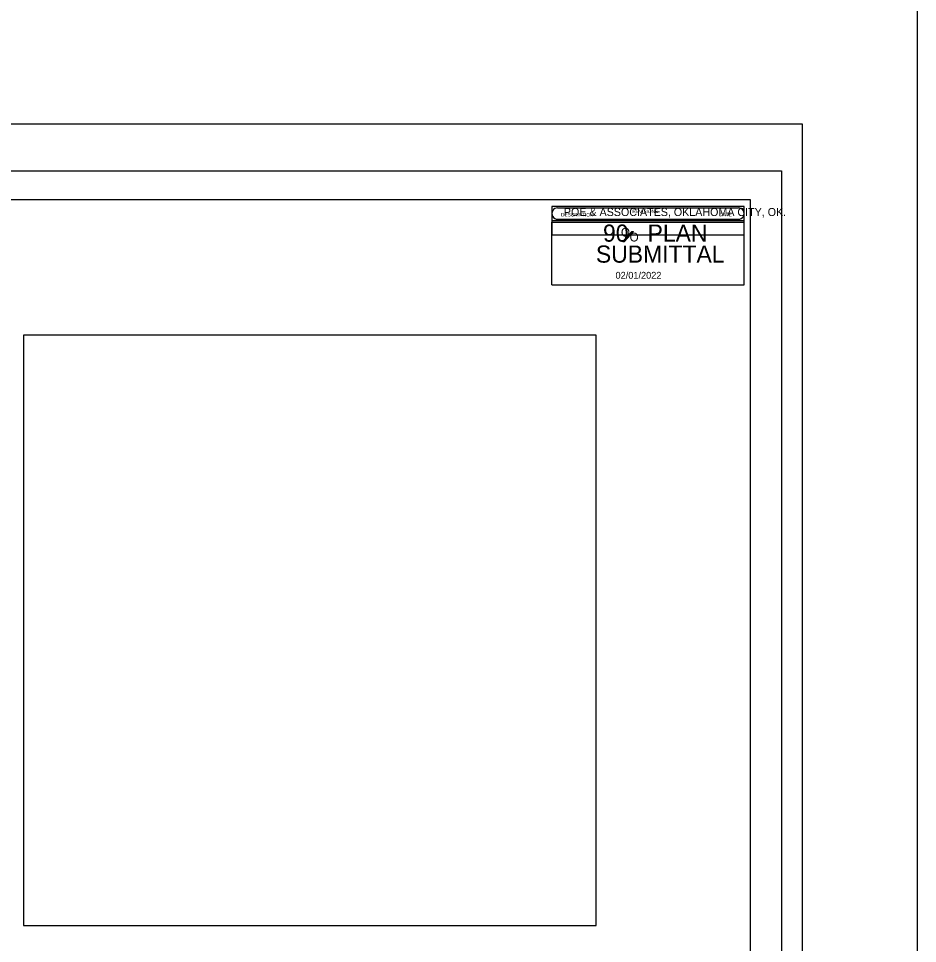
# Model space of a CAD drawing. Extents: x 12310.9 to 12354.4, y 579 to 640.5.
# Drawn here: x 12338.64 to 12354.38, y 594.26 to 610.44 of the extents above; entities that cross this region are included whole.
import ezdxf

# ---------------------------------------------------------------- set-up
doc = ezdxf.new("R2010")
doc.units = 0
for name, color, linetype in [('Default', 7, 'Continuous'), ('S', 7, 'Continuous'), ('SHT_Plot_Shape_Full', 7, 'Continuous'), ('SHT_Plot_Shape_Half', 7, 'Continuous'), ('SHT_Sheet_Border', 7, 'Continuous'), ('SHT_Stamp_90_Submit', 7, 'Continuous'), ('SHT_Stamp_Rev_Block', 7, 'Continuous')]:
    doc.layers.add(name, color=color, linetype=linetype)

msp = doc.modelspace()

# ---------------------------------------------------------------- linework, layer by layer
at = {"layer": 'Default'}
msp.add_lwpolyline([(12338.726, 594.572), (12348.754, 594.572), (12348.754, 604.905), (12338.726, 604.905)], close=True, dxfattribs=at)
at = {"layer": 'S'}
msp.add_lwpolyline([(12354.38, 640.488), (12310.944, 640.488), (12310.944, 579.031), (12354.38, 579.031)], close=True, dxfattribs=at)
at = {"layer": 'SHT_Plot_Shape_Full'}
msp.add_lwpolyline([(12316.36, 608.6), (12352.36, 608.6), (12352.36, 584.6), (12316.36, 584.6)], close=True, dxfattribs=at)
at = {"layer": 'SHT_Plot_Shape_Half'}
msp.add_lwpolyline([(12317.998, 607.775), (12351.998, 607.775), (12351.998, 585.775), (12317.998, 585.775)], close=True, dxfattribs=at)
at = {"layer": 'SHT_Sheet_Border'}
msp.add_lwpolyline([(12351.448, 586.275), (12319.948, 586.275), (12319.948, 607.275), (12351.448, 607.275)], close=True, dxfattribs=at)
at = {"layer": 'SHT_Stamp_90_Submit'}
for p, q in [((12348.079, 607.13), (12351.245, 607.13)), ((12347.979, 606.88), (12351.345, 606.88)), ((12347.979, 605.781), (12347.979, 606.88)), ((12348.079, 606.93), (12351.245, 606.93)), ((12351.345, 605.781), (12351.345, 606.88)), ((12349.222, 606.542), (12349.377, 606.714)), ((12349.24, 606.542), (12349.395, 606.714)), ((12349.245, 606.542), (12349.4, 606.714)), ((12349.252, 606.542), (12349.408, 606.714)), ((12349.377, 606.714), (12349.408, 606.714)), ((12349.222, 606.542), (12349.252, 606.542)), ((12347.979, 605.781), (12351.345, 605.781))]:
    msp.add_line(p, q, dxfattribs=at)
for centre, start, end in [((12348.079, 607.03), 89.9952, 270), ((12351.245, 607.03), 270, 90.0048)]:
    msp.add_arc(centre, 0.1, start, end, dxfattribs=at)
at = {"layer": 'SHT_Stamp_Rev_Block'}
for p, q in [((12347.979, 607.151), (12347.979, 606.651)), ((12351.345, 607.151), (12347.979, 607.151)), ((12351.345, 606.651), (12351.345, 607.151)), ((12351.345, 606.901), (12347.979, 606.901)), ((12351.345, 606.651), (12347.979, 606.651))]:
    msp.add_line(p, q, dxfattribs=at)

# ---------------------------------------------------------------- texts
at = {"layer": 'SHT_Stamp_90_Submit'}
for s, height, p in [('POE & ASSOCIATES, OKLAHOMA CITY, OK.', 0.14, (12348.189, 606.987)), ('90   PLAN', 0.3, (12348.874, 606.538)), ('O', 0.153, (12349.187, 606.627)), ('O', 0.153, (12349.339, 606.542)), ('SUBMITTAL', 0.3, (12348.75, 606.171)), ('02/01/2022', 0.12, (12349.093, 605.89))]:
    msp.add_text(s, height=height, rotation=360, dxfattribs=at).set_placement(p)
at = {"layer": 'SHT_Stamp_Rev_Block'}
for s, p in [('DESCRIPTION', (12348.139, 606.979)), ('REVISIONS', (12349.388, 607.038)), ('DATE', (12350.908, 606.983))]:
    msp.add_text(s, height=0.06, dxfattribs=at).set_placement(p)

doc.saveas('drawing.dxf')
